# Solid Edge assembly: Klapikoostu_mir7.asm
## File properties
Author: Türk
Template: Iso Assembly.asm
Last saved by: Türk
Revision: 3
Application: Solid Edge
Username: Türk
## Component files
Klapp.par
Klapi vedru_mir2.par
Klapipuks.par
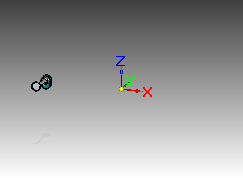
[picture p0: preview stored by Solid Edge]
